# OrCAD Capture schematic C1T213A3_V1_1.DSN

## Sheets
1 000_Log: title: TELINK; rev: V1.1; note: C1T213A3
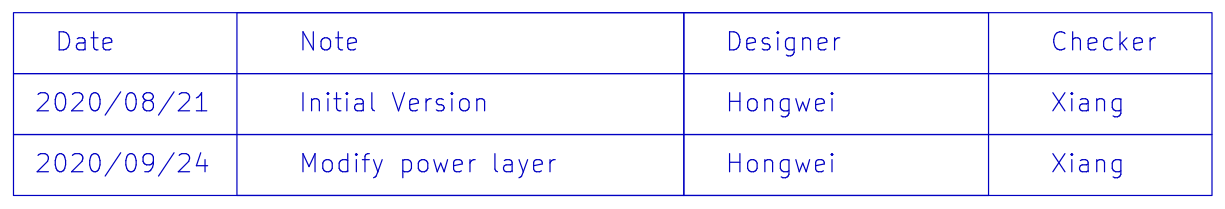
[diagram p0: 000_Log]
2 001_MAIN: size A3
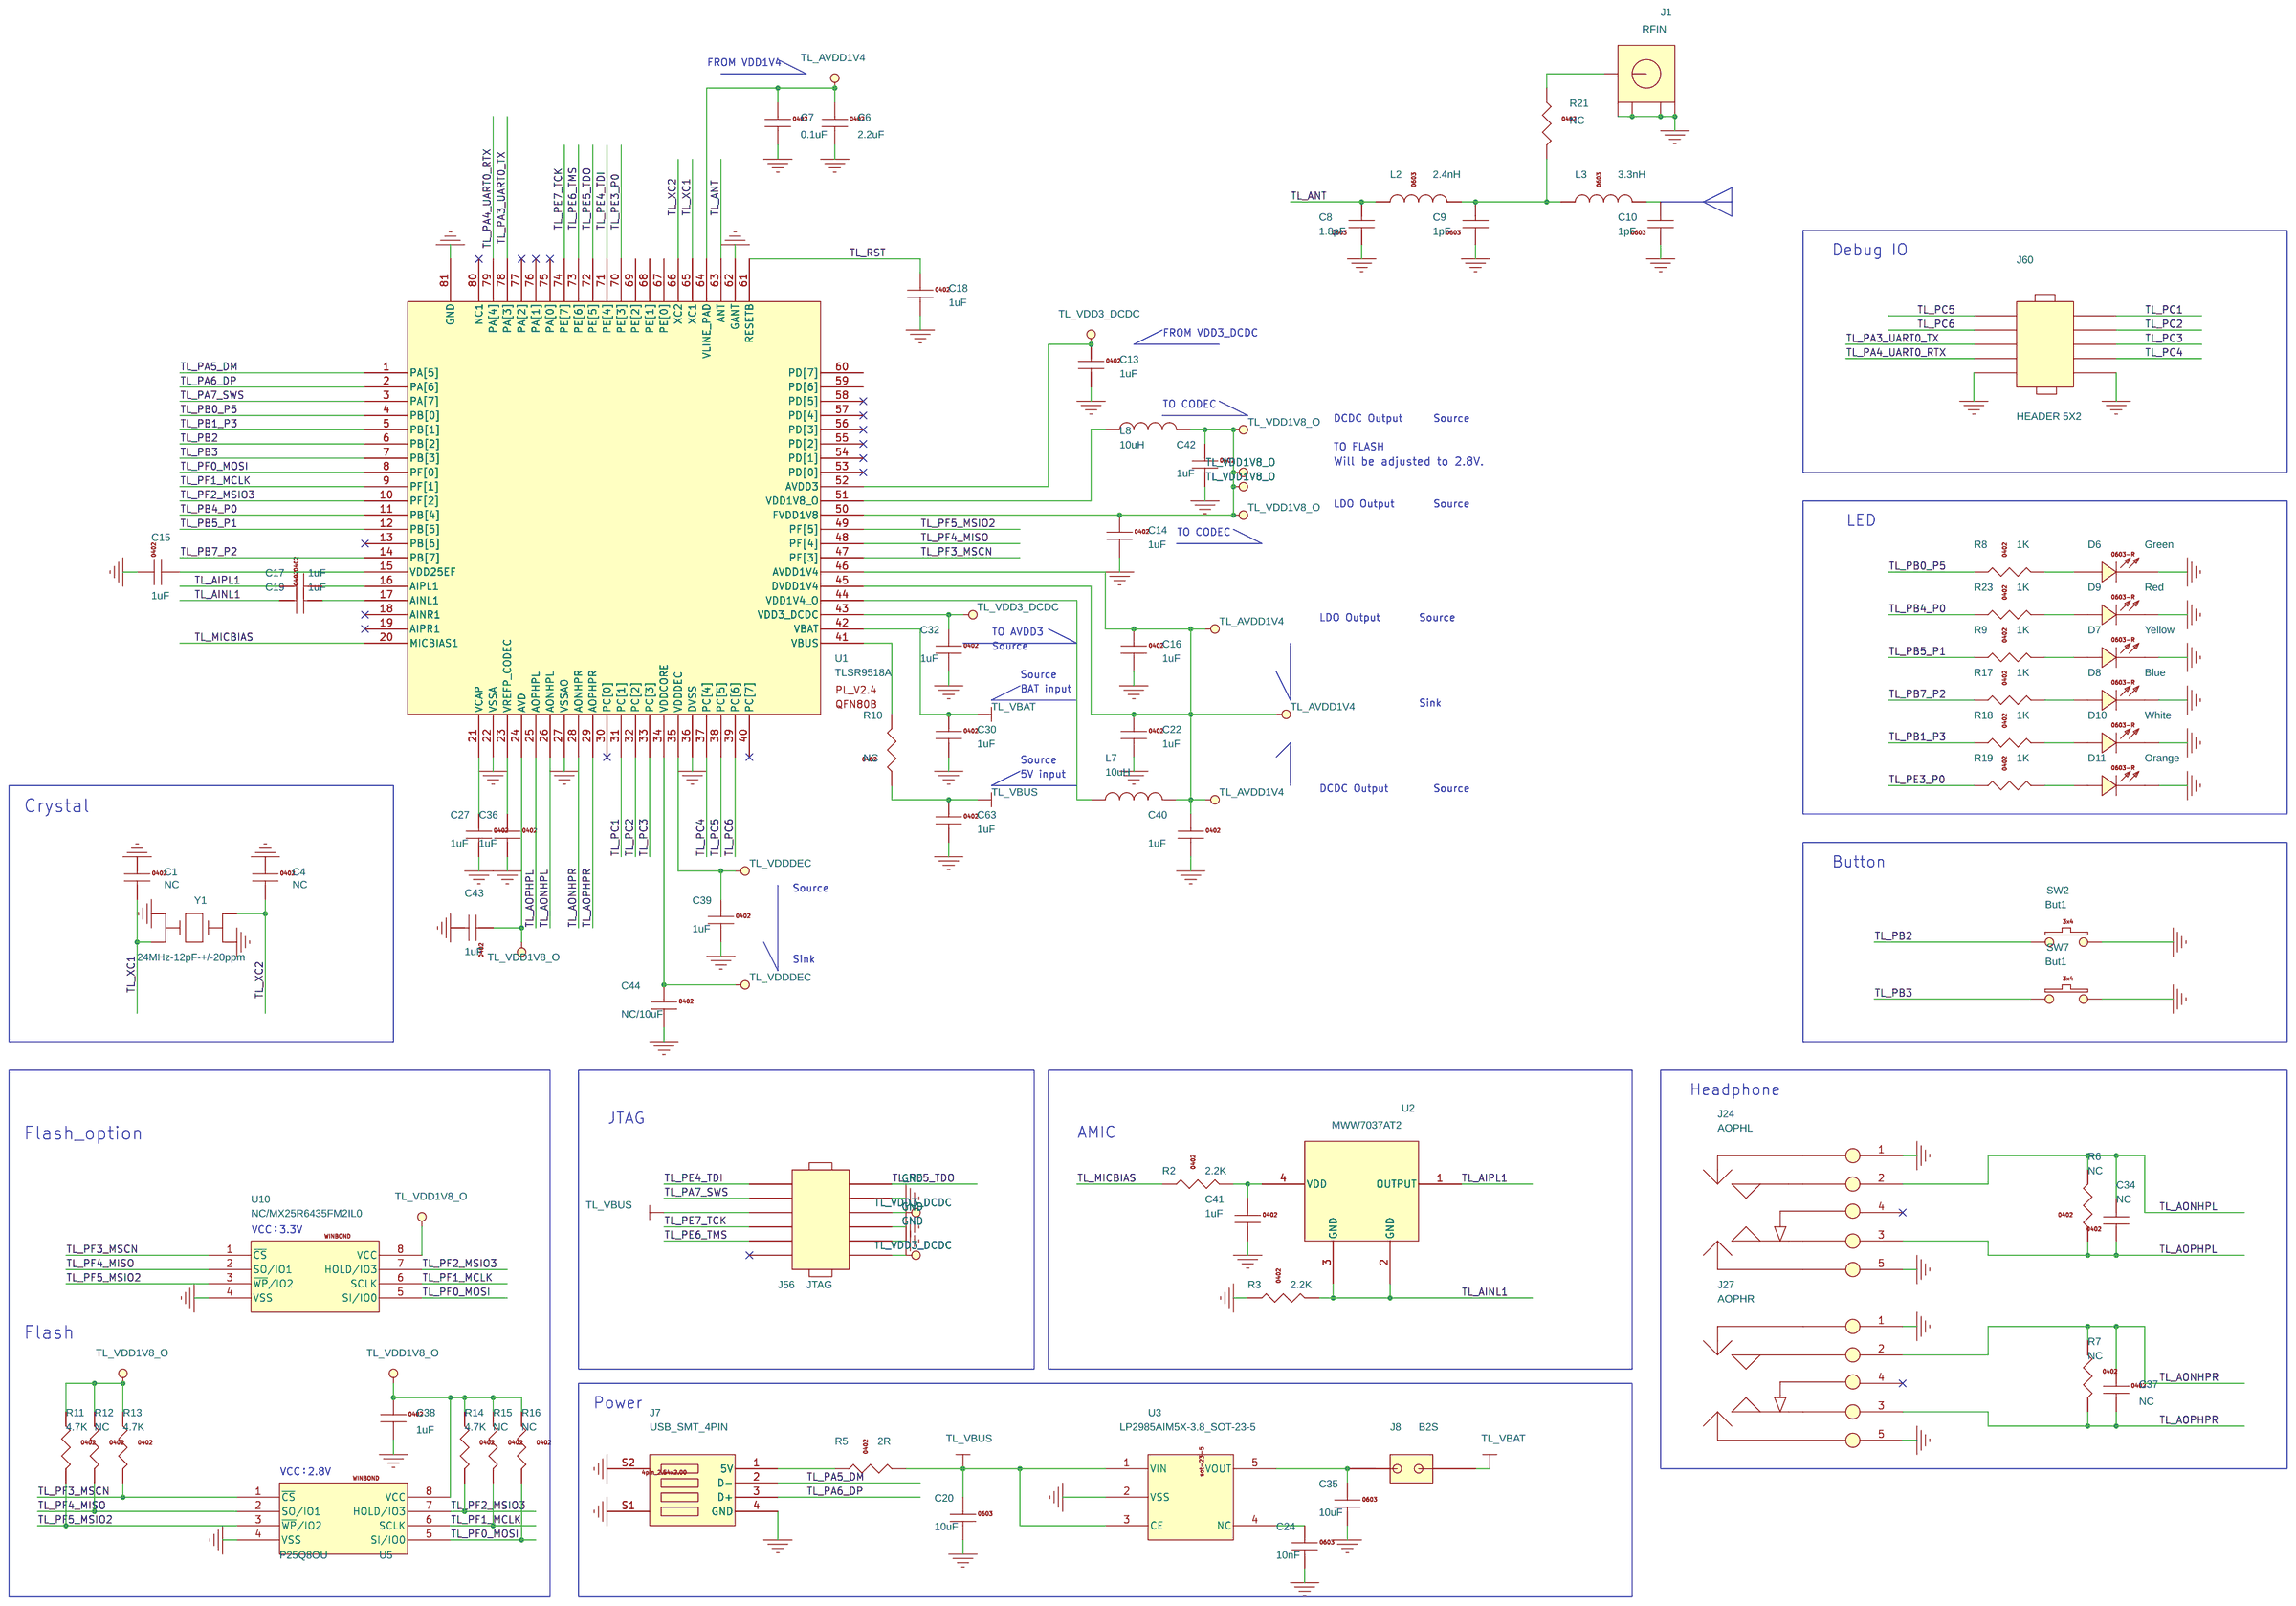
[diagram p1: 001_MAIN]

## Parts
C1  NC  [0402]
C4  NC  [0402]
C6  2.2uF  [0402]
C7  0.1uF  [0402]
C8  1.8pF  [0402]
C9  1pF  [0402]
C10  1pF  [0402]
C13  1uF  [0402]
C14  1uF  [0402]
C15  1uF  [0402]
C16  1uF  [0402]
C17  1uF  [0402]
C18  1uF  [0402]
C19  1uF  [0402]
C20  10uF  [0603C]
C22  1uF  [0402]
C24  10nF  [0402]
C27  1uF  [0402]
C30  1uF  [0402]
C32  1uF  [0402]
C34  NC  [0402]
C35  10uF  [0603C]
C36  1uF  [0402]
C37  NC  [0402]
C38  1uF  [0402]
C39  1uF  [0402]
C40  1uF  [0402]
C41  1uF  [0402]
C42  1uF  [0402]
C43  1uF  [0402]
C44  NC/10uF  [0603C]
C63  1uF  [0402]
D6  Green  [0603-LED]
D7  Yellow  [0603-LED]
D8  Blue  [0603-LED]
D9  Red  [0603-LED]
D10  White  [0603-LED]
D11  Orange  [0603-LED]
J1  RFIN  [SMA-H]
J7  USB_SMT_4PIN  [usb-m-4]
J8  B2S  [HDR254F-1X2X850]
J24  AOPHL  [PJ-327]
J27  AOPHR  [PJ-327]
J56  JTAG  [hdr254f-2x6x850]
J60  HEADER 5X2  [hdr254f-2x5x850]
L2  2.4nH  [0402]
L3  3.3nH  [0402]
L7  10uH  [1008L]
L8  10uH  [1008L]
R2  2.2K  [0402]
R3  2.2K  [0402]
R5  2R  [0402]
R6  NC  [0402]
R7  NC  [0402]
R8  1K  [0402]
R9  1K  [0402]
R10  NC  [0402]
R11  4.7K  [0402]
R12  NC  [0402]
R13  4.7K  [0402]
R14  4.7K  [0402]
R15  NC  [0402]
R16  NC  [0402]
R17  1K  [0402]
R18  1K  [0402]
R19  1K  [0402]
R21  NC  [0402]
R23  1K  [0402]
SW2  But1  [butsmd2px4_00y3_00_nh]
SW7  But1  [butsmd2px4_00y3_00_nh]
U1  TLSR9518A  [qfn_9x9_80pin_0p4_6p10x6p10]
U2  MWW7037AT2  [ga_bfa423_a83]
U3  LP2985AIM5X-3.8_SOT-23-5  [sot-23-5]
U5  P25Q8OU  [W25X10_20_40BL]
U10  NC/MX25R6435FM2IL0  [sop8_208mil]
Y1  24MHz-12pF-+/-20ppm  [OSCCC250X320X110]

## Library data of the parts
C1 C4 = C1005_NC
C6 C7 C13-C16 C18 C22 C27 C30 C32 C36 C38-C44 C63 = C1005X5R1C104K
C8-C10 = C1608_NC
C17 C19 C34 C37 = C1005X5R1C105K
C20 C24 C35 = C1608X5R0J106M
D6-D11 = 0603D_Red
J1 = SMA_JACK_2: PART: RF
J7 = USB_SMT_1
J8 = B2S_0
J24 J27 = PJ327_2
J56 = HEADER_6X2
J60 = HEADER_5X2
L2 L3 = MLK1608_000R
L7 L8 = IND
R2 R3 R6 R7 R11-R16 = RS0402K104JT
R5 = RS0402K100JT
R8-R10 R17-R19 R21 R23 = RS0402K332JT
SW2 SW7 = SW2PIN_3x4
U1 = TLSR9518A
U2 = MULPS4CX-RM5_0
U3 = XC6219_1.3V_SOT-23-5
U5 U10 = GD25LD40C_0
Y1 = CRYSTAL4_SM_0

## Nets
GND: C1.1 C4.1 C6.2 C7.2 C8.1 C9.1 C10.1 C13.2 C14.2 C15.1 C16.2 C18.2 C20.2 C22.2 C24.2 C27.2 C30.2 C32.2 C35.2 C36.2 C38.2 C39.2 C40.2 C41.2 C42.2 C43.2 C44.2 C63.2 D6.C(CATHODE) D7.C(CATHODE) D8.C(CATHODE) D9.C(CATHODE) D10.C(CATHODE) D11.C(CATHODE) J1.2 J1.3 J1.4 J1.5 J7.4(GND) J7.S1 J7.S2 J24.1 J24.5 J27.1 J27.5 J56.3 J56.5 J56.9 J60.9 J60.10 R3.1 SW2.2 SW7.2 U1.22(VSSA) U1.27(VSSAO) U1.36(DVSS) U1.62(GANT) U1.81(GND) U3.2(VSS) U5.4(VSS) U10.4(VSS) Y1.2 Y1.4
TL_AINL1: C19.1 R3.2 U2.2(GND) U2.3(GND)
TL_AIPL1: C17.1 U2.1(OUTPUT)
TL_ANT: C8.2 L2.1 U1.63(ANT)
TL_AONHPL: C34.2 J24.2 R6.2 U1.26(AONHPL)
TL_AONHPR: C37.1 J27.2 R7.1 U1.28(AONHPR)
TL_AOPHPL: C34.1 J24.3 R6.1 U1.25(AOPHPL)
TL_AOPHPR: C37.2 J27.3 R7.2 U1.29(AOPHPR)
TL_AVD: C14.1 C38.1 C42.1 C43.1 L8.2 R11.1 R12.1 R13.1 R14.1 R15.1 R16.1 U1.24(AVD) U1.50(FVDD1V8) U5.8(VCC) U10.8(VCC)
TL_AVDD1V4: C6.1 C7.1 C16.1 C22.1 C40.1 L7.2 U1.45(DVDD1V4) U1.46(AVDD1V4) U1.64(VLINE_PAD)
TL_MICBIAS: R2.1 U1.20(MICBIAS1)
TL_PA3_UART0_TX: J60.6 U1.78(PA[3])
TL_PA4_UART0_RTX: J60.8 U1.79(PA[4])
TL_PA5_DM: J7.2(D-) U1.1(PA[5])
TL_PA6_DP: J7.3(D+) U1.2(PA[6])
TL_PA7_SWS: J56.10 U1.3(PA[7])
TL_PB0_P5: R8.1 U1.4(PB[0])
TL_PB1_P3: R18.1 U1.5(PB[1])
TL_PB2: SW2.1 U1.6(PB[2])
TL_PB3: SW7.1 U1.7(PB[3])
TL_PB4_P0: R23.1 U1.11(PB[4])
TL_PB5_P1: R9.1 U1.12(PB[5])
TL_PB7_P2: R17.1 U1.14(PB[7])
TL_PC1: J60.1 U1.31(PC[1])
TL_PC2: J60.3 U1.32(PC[2])
TL_PC3: J60.5 U1.33(PC[3])
TL_PC4: J60.7 U1.37(PC[4])
TL_PC5: J60.2 U1.38(PC[5])
TL_PC6: J60.4 U1.39(PC[6])
TL_PE3_P0: R19.1 U1.70(PE[3])
TL_PE4_TDI: J56.12 U1.71(PE[4])
TL_PE5_TDO: J56.11 U1.72(PE[5])
TL_PE6_TMS: J56.4 U1.73(PE[6])
TL_PE7_TCK: J56.6 U1.74(PE[7])
TL_PF0_MOSI: R16.2 U1.8(PF[0]) U5.5(SI/IO0) U10.5(SI/IO0)
TL_PF1_MCLK: R15.2 U1.9(PF[1]) U5.6(SCLK) U10.6(SCLK)
TL_PF2_MSIO3: R14.2 U1.10(PF[2]) U5.7(HOLD/IO3) U10.7(HOLD/IO3)
TL_PF3_MSCN: R13.2 U1.47(PF[3]) U5.1(~{CS}) U10.1(~{CS})
TL_PF4_MISO: R12.2 U1.48(PF[4]) U5.2(SO/IO1) U10.2(SO/IO1)
TL_PF5_MSIO2: R11.2 U1.49(PF[5]) U5.3(~{WP}/IO2) U10.3(~{WP}/IO2)
TL_RST: C18.1 U1.61(RESETB)
TL_VBAT: C30.1 J8.2 U1.42(VBAT)
TL_VBUS: C20.1 C63.1 J56.8 R5.2 R10.1 U3.1(VIN) U3.3(CE)
TL_VDD3_DCDC: C13.1 C32.1 J56.1 J56.7 U1.43(VDD3_DCDC) U1.52(AVDD3)
TL_VDDDEC: C39.1 C44.1 U1.34(VDDCORE) U1.35(VDDDEC)
TL_XC1: C1.2 U1.65(XC1) Y1.3
TL_XC2: C4.2 U1.66(XC2) Y1.1
N19932090: C9.2 L2.2 L3.1 R21.2
N19932678: D6.A(ANODE) R8.2
N19932682: D7.A(ANODE) R9.2
N19932684: D8.A(ANODE) R17.2
N19932722: D9.A(ANODE) R23.2
N19933805: C24.1 U3.4(NC)
N19933807: C35.1 J8.1 U3.5(VOUT)
N19933809: J7.1(5V) R5.1
N19934408: C41.1 R2.2 U2.4(VDD)
N19952247: C17.2 U1.16(AIPL1)
N19952336: C19.2 U1.17(AINL1)
N19954124: L8.1 U1.51(VDD1V8_O)
N19954165: L7.1 U1.44(VDD1V4_O)
N19959102: C36.1 U1.23(VREFP_CODEC)
N19959110: C27.1 U1.21(VCAP)
N19961012: C15.2 U1.15(VDD25EF)
N19962035: R10.2 U1.41(VBUS)
N19963346: J1.1 R21.1
N19965304: C10.2 L3.2
N19973716: D10.A(ANODE) R18.2
N19973830: D11.A(ANODE) R19.2

Not connected (* = marked no-connect by the designer): J24 4*; J27 4*; J56 2*; U1 13(PB[6])* 18(AINR1)* 19(AIPR1)* 30(PC[0])* 40(PC[7])* 53(PD[0])* 54(PD[1])* 55(PD[2])* 56(PD[3])* 57(PD[4])* 58(PD[5])* 59(PD[6]) 60(PD[7]) 67(PE[0]) 68(PE[1]) 69(PE[2]) 75(PA[0])* 76(PA[1])* 77(PA[2])* 80(NC1)*

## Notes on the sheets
sheet 1
- Date
- Note
- Designer
- Checker
- 2020/08/21
- Initial Version
- Hongwei
- Xiang
- 2020/09/24
- Modify power layer
- Hongwei
- Xiang
sheet 2
- FROM VDD1V4
- Debug IO
- FROM VDD3_DCDC
- TO CODEC
- DCDC Output
- Source
- TO FLASH
- Will be adjusted to 2.8V.
- LDO Output
- Source
- TO CODEC
- LED
- LDO Output
- Source
- TO AVDD3
- Source
- Source
- BAT input
- Sink
- Source
- 5V input
- Crystal
- DCDC Output
- Source
- Button
- Source
- Sink
- Headphone
- JTAG
- Flash_option
- AMIC
- VCC：3.3V
- Flash
- Power
- VCC：2.8V
